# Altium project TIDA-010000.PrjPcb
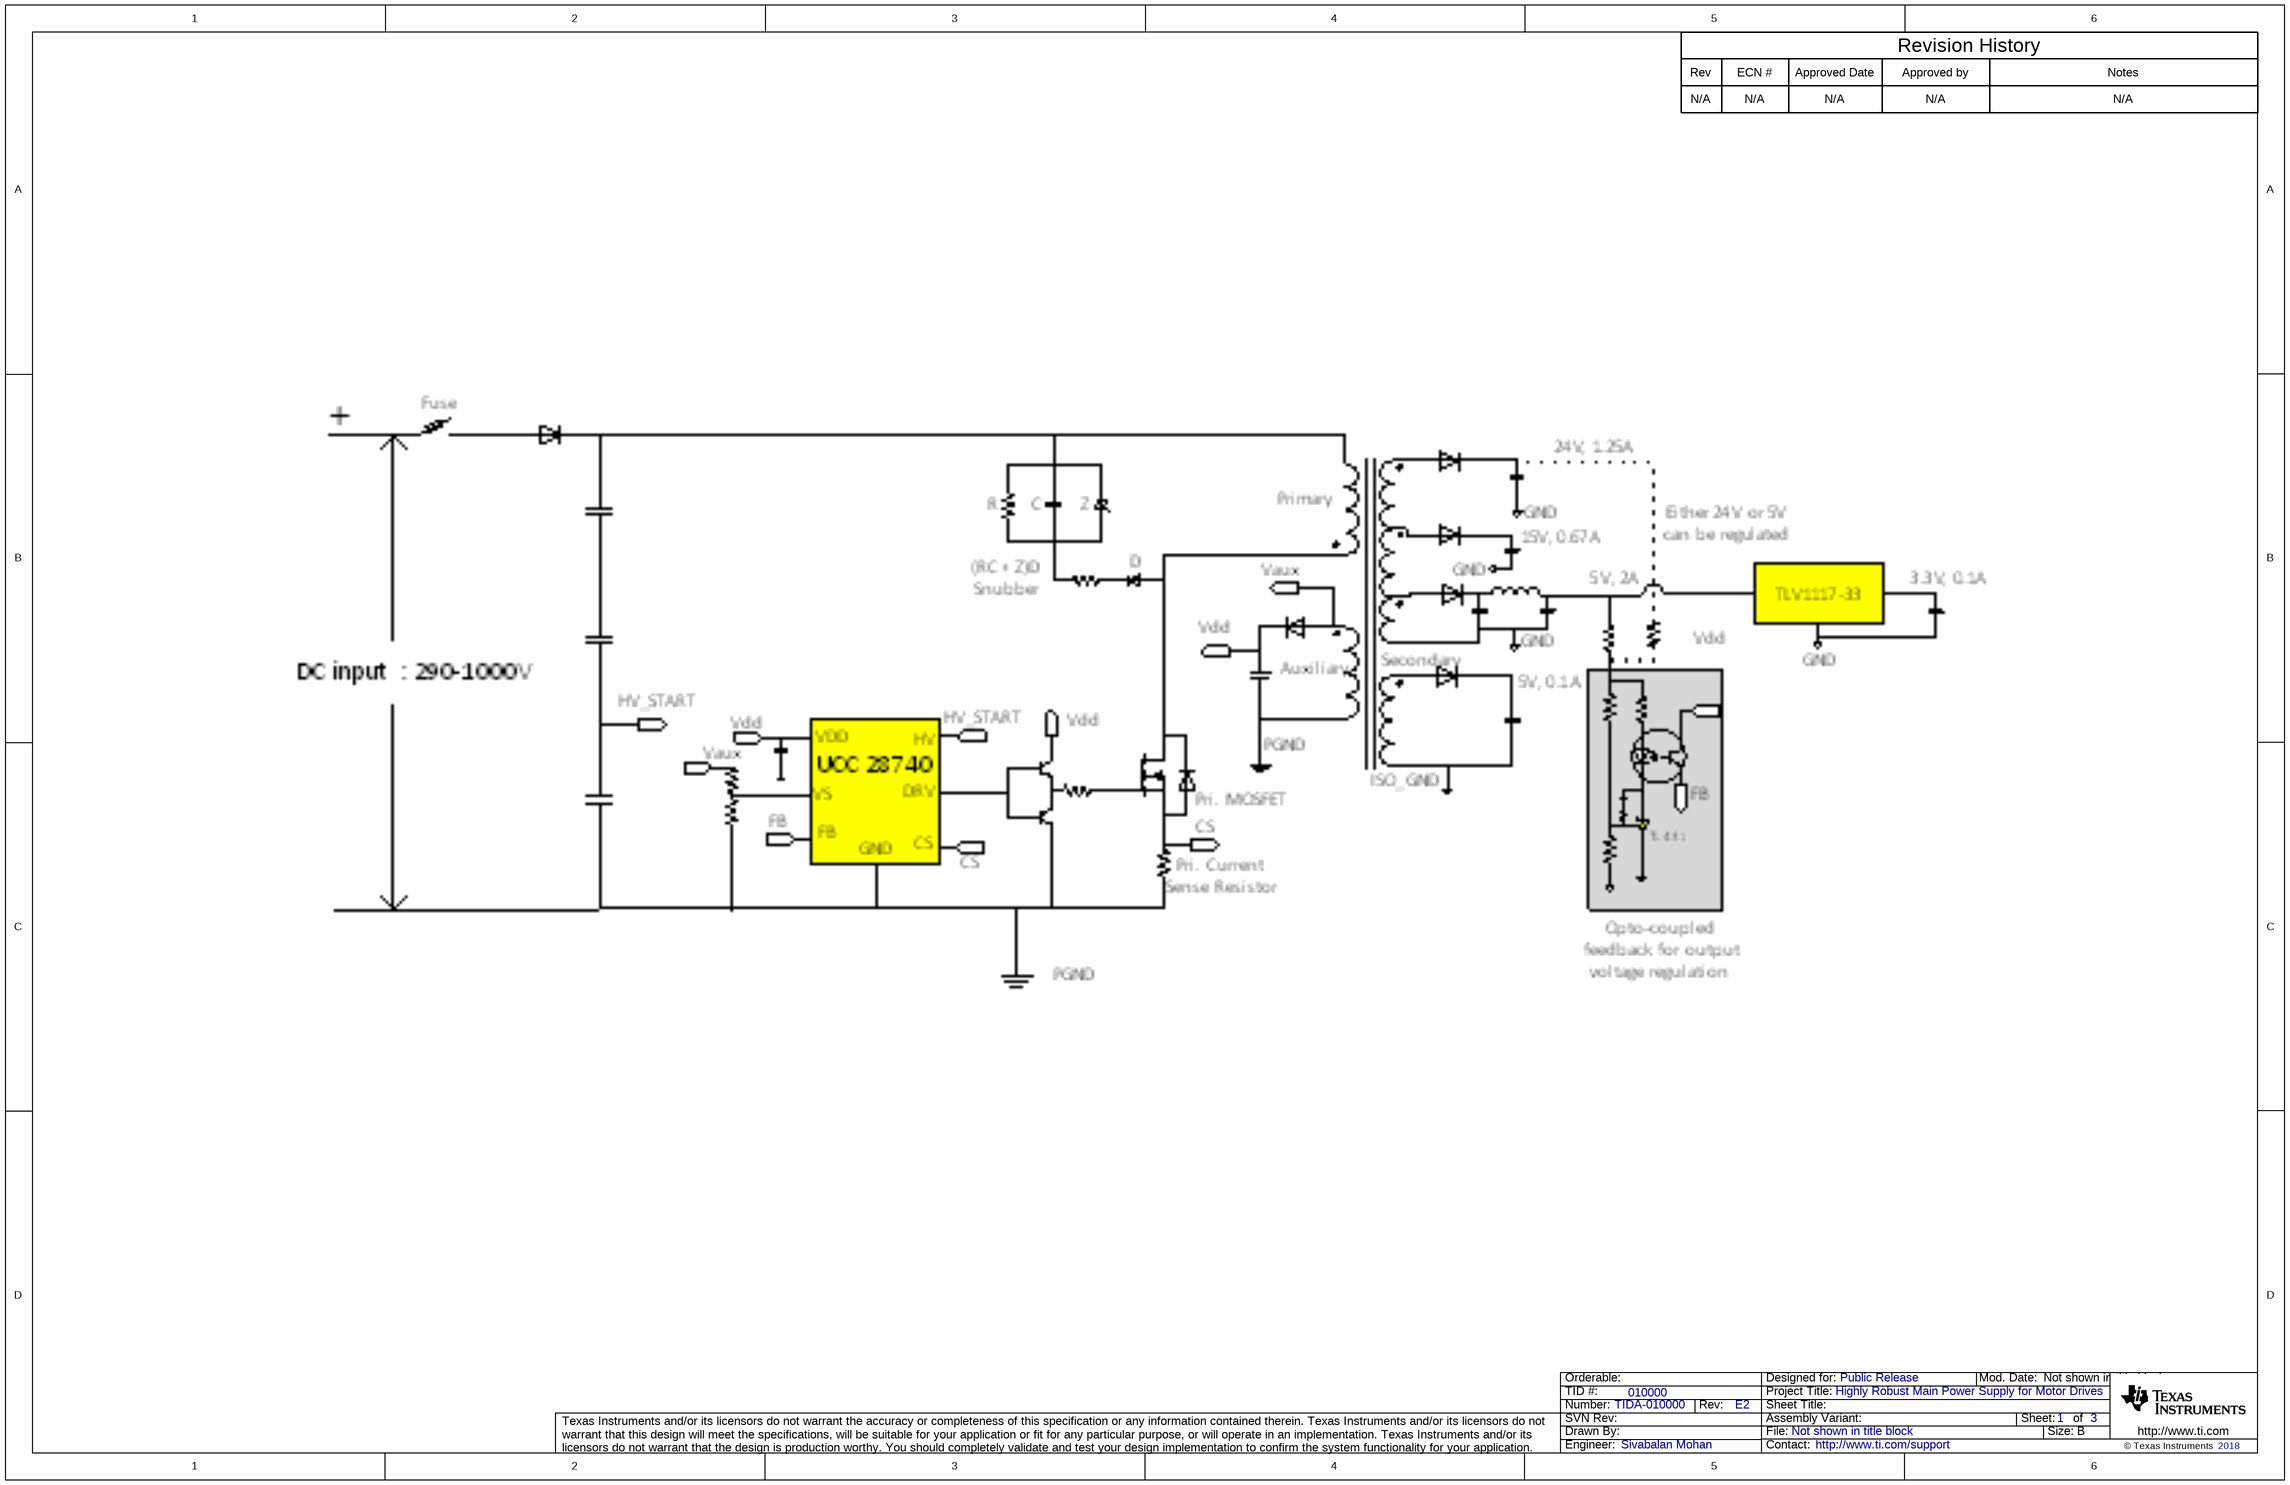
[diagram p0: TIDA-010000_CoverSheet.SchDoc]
CopyrightYear: 2018; PCB_Layout: Shashaank; PCB_Rev: E2; PRJ_Customer: Public Release; PRJ_Engineer: Sivabalan Mohan; PRJ_Number: TIDA-010000; PRJ_Title: Highly Robust Main Power Supply for Motor Drives; SCH_Rev: E2; TechSupport: http://www.ti.com/support; TID: 010000
3 sheets, 147 parts. Net scope: global (net labels, ports and power ports of the same name join across sheets).
Board file: TIDA-010000.PcbDoc
Sheets:
  TIDA-010000_CoverSheet.SchDoc
  TIDA-010000_Flyback Converter.SchDoc
  TIDA-010000_EVM_Hardware.SchDoc

## Sheet TIDA-010000_CoverSheet.SchDoc
size 431 x 279 mm; Date: Not shown in title block; ApprovedBy: Not shown in title block; CheckedBy: Not shown in title block; Author: Not shown in title block; CompanyName: Not shown in title block; Engineer: Not shown in title block; Organization: Not shown in title block; Address1: Not shown in title block; Address2: Not shown in title block; Address3: Not shown in title block; Address4: Not shown in title block; DocumentNumber: 1; Revision: Use project parameter SCH_Rev; SheetNumber: 1; SheetTotal: 3; PageSetup: Record=PageOptions¦CenterHorizontal=True¦CenterVertical=True¦PrintScale=1.00¦XCorrection=1.00¦YCorrection=1.00¦PrintKind=0¦BorderSize=5000000¦LeftOffset=0¦BottomOffset=0¦Orientation=2¦PaperLength=1000¦PaperWidth=1000¦Scale=100¦PaperSource=15¦PrintQuality=600¦MediaType=1¦DitherType=10¦PaperKind=Letter¦PrintScaleMode=1

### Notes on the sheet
- Rev
- N/A
- ECN #
- Approved Date
- Approved by
- Revision History
- Notes

## Sheet TIDA-010000_Flyback Converter.SchDoc
size 431 x 279 mm; Date: Not shown in title block; ApprovedBy: Not shown in title block; CheckedBy: Not shown in title block; Author: Not shown in title block; CompanyName: Not shown in title block; Engineer: Not shown in title block; Organization: Not shown in title block; Address1: Not shown in title block; Address2: Not shown in title block; Address3: Not shown in title block; Address4: Not shown in title block; DocumentNumber: 1; Revision: Use project parameter SCH_Rev; SheetNumber: 2; SheetTotal: 3; PageSetup: Record=PageOptions¦CenterHorizontal=True¦CenterVertical=True¦PrintScale=1.00¦XCorrection=1.00¦YCorrection=1.00¦PrintKind=0¦BorderSize=5000000¦LeftOffset=0¦BottomOffset=0¦Orientation=2¦PaperLength=1000¦PaperWidth=1000¦Scale=100¦PaperSource=15¦PrintQuality=600¦MediaType=1¦DitherType=10¦PaperKind=Letter¦PrintScaleMode=1
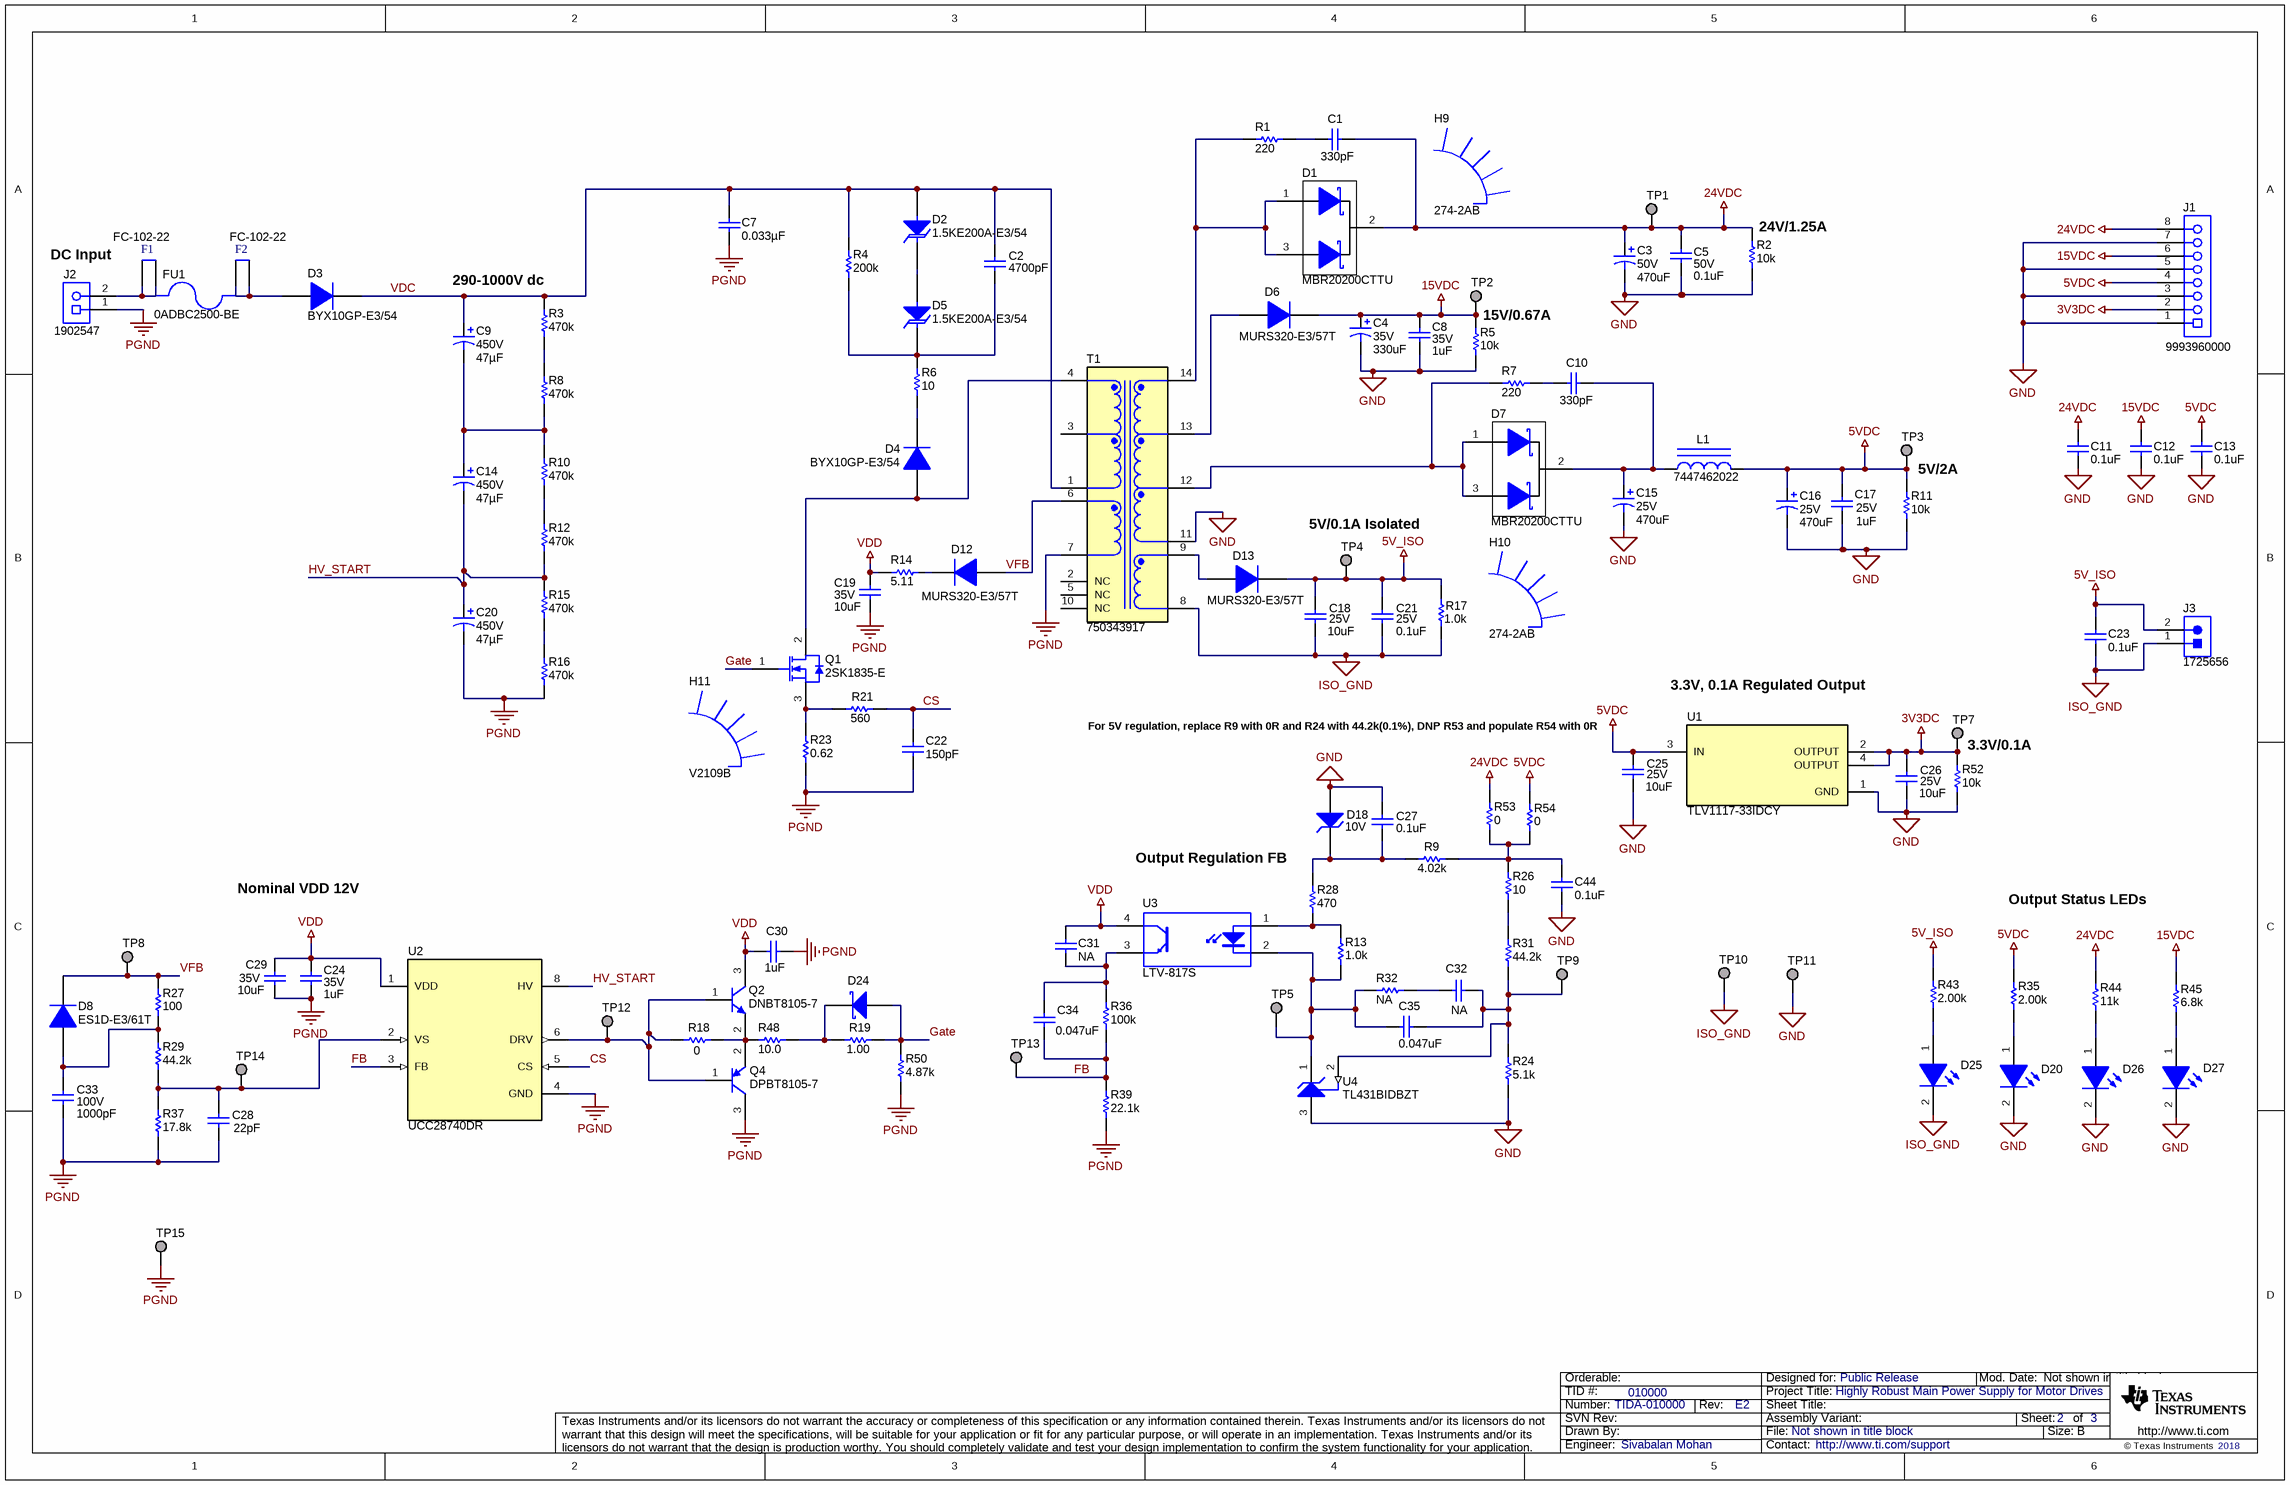
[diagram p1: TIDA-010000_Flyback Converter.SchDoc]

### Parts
C1  ValueDisplayed: 330pF  [1206]  (hidden comment: GRM31A5C2J331JW01D)
C2  ValueDisplayed: 4700pF  [1206]  (hidden comment: GRM31BR73A472KW01L)
C3  VDC_V: 50V  ValueDisplayed: 470uF  [BT_1250x2500]  (hidden comment: UBT1H471MHD1TO)
C4  VDC_V: 35V  ValueDisplayed: 330uF  [BT_1000x2000]  (hidden comment: UBT1V331MPD1TD)
C5  Value2: 50V  ValueDisplayed: 0.1uF  [0805_HV]  (hidden comment: C0805C104K5RACTU)
C7  ValueDisplayed: 0.033µF  [B32672_1800x900x1750]  (hidden comment: B32672L1333J000)
C8  VDC_V: 35V  ValueDisplayed: 1uF  [0603]  (hidden comment: GMK107AB7105KAHT)
C9  VDC_V: 450V  ValueDisplayed: 47µF  [BXW_1250x3500]  (hidden comment: 450BXW47MEFC12.5X35)
C10  ValueDisplayed: 330pF  [1206]  (hidden comment: GRM31A5C2J331JW01D)
C11  ValueDisplayed: 0.1uF  [0805_HV]  (hidden comment: C0805C104K5RACTU)
C12  ValueDisplayed: 0.1uF  [0805_HV]  (hidden comment: C0805C104K5RACTU)
C13  ValueDisplayed: 0.1uF  [0805_HV]  (hidden comment: C0805C104K5RACTU)
C14  VDC_V: 450V  ValueDisplayed: 47µF  [BXW_1250x3500]  (hidden comment: 450BXW47MEFC12.5X35)
C15  VDC_V: 25V  ValueDisplayed: 470uF  [BT_1000x2000]  (hidden comment: UBT1E471MPD1TD)
C16  VDC_V: 25V  ValueDisplayed: 470uF  [BT_1000x2000]  (hidden comment: UBT1E471MPD1TD)
C17  VDC_V: 25V  ValueDisplayed: 1uF  [0805_HV]  (hidden comment: GRM219R71E105KA88D)
C18  VDC_V: 25V  ValueDisplayed: 10uF  [1206_190]  (hidden comment: C3216X7R1E106M160AE)
C19  VDC_V: 35V  ValueDisplayed: 10uF  [1206_180]  (hidden comment: C3216X7R1V106K160AC)
C20  VDC_V: 450V  ValueDisplayed: 47µF  [BXW_1250x3500]  (hidden comment: 450BXW47MEFC12.5X35)
C21  VDC_V: 25V  ValueDisplayed: 0.1uF  [0603]  (hidden comment: C1608X7R1E104K080AA)
C22  ValueDisplayed: 150pF  [0201]  (hidden comment: GRM033R71E151KA01D)
C23  ValueDisplayed: 0.1uF  [0805_HV]  (hidden comment: C0805C104K5RACTU)
C24  VDC_V: 35V  ValueDisplayed: 1uF  [0603]  (hidden comment: GMK107AB7105KAHT)
C25  VDC_V: 25V  ValueDisplayed: 10uF  [1206_190]  (hidden comment: C3216X7R1E106M160AE)
C26  VDC_V: 25V  ValueDisplayed: 10uF  [1206_190]  (hidden comment: C3216X7R1E106M160AE)
C27  ValueDisplayed: 0.1uF  [0805_HV]  (hidden comment: C0805C104K5RACTU)
C28  ValueDisplayed: 22pF  [0201_033]  (hidden comment: GCM0335C1E220JD03D)
C29  VDC_V: 35V  ValueDisplayed: 10uF  [1206_180]  (hidden comment: C3216X7R1V106K160AC)
C30  ValueDisplayed: 1uF  [0603]  (hidden comment: GMK107AB7105KAHT)
C31  ValueDisplayed: NA  [0805_HV]  (hidden comment: C2012X7R1H474K125AB)
C32  ValueDisplayed: NA  [0805_HV]  (hidden comment: C2012X7R1H474K125AB)
C33  Value2: 100V  ValueDisplayed: 1000pF  [0603]  (hidden comment: C1608X7R2A102K080AA)
C34  ValueDisplayed: 0.047uF  [0805_HV]  (hidden comment: 08055C473JAT2A)
C35  ValueDisplayed: 0.047uF  [0805_HV]  (hidden comment: 08055C473JAT2A)
C44  ValueDisplayed: 0.1uF  [0805_HV]  (hidden comment: C0805C104K5RACTU)
D1  MBR20200CTTU  [TO-220AB]
D2  1.5KE200A-E3/54  [DO-201AA_Vertical]
D3  BYX10GP-E3/54  [DO-41]
D4  BYX10GP-E3/54  [DO-41]
D5  1.5KE200A-E3/54  [DO-201AA_Vertical]
D6  MURS320-E3/57T  [SMC]
D7  MBR20200CTTU  [TO-220AB]
D8  ES1D-E3/61T  [SMA]
D12  MURS320-E3/57T  [SMC]
D13  MURS320-E3/57T  [SMC]
D18  value 10V  [SOD-523]  (hidden comment: BZT52C10T-7)
D20  LG L29K-G2J1-24-Z  [LG L29K_GREEN]  (value not drawn)
D24  BAT41ZFILM  [SOD-123]  (value not drawn)
D25  LG L29K-G2J1-24-Z  [LG L29K_GREEN]  (value not drawn)
D26  LG L29K-G2J1-24-Z  [LG L29K_GREEN]  (value not drawn)
D27  LG L29K-G2J1-24-Z  [LG L29K_GREEN]  (value not drawn)
F1  FC-102-22  [BelFuse_FC-102-22]
F2  FC-102-22  [BelFuse_FC-102-22]
FU1  0ADBC2500-BE  (mechanical)
H9  274-2AB  [HSINK_274-2AB]
H10  274-2AB  [HSINK_274-2AB]
H11  V2109B  [Assman_V2109B]
J1  9993960000  [Weidmuller_9993960000]
J2  1902547  [Phoenix_1902547]
J3  1725656  [CONN_1725656]
L1  7447462022  [WE-TI_5075]
Q1  2SK1835-E  [TO-3P]
Q2  DNBT8105-7  [SOT-23]
Q4  DPBT8105-7  [SOT-23]
R1  ValueDisplayed: 220  [2010]  (hidden comment: CRCW2010220RJNEF)
R2  ValueDisplayed: 10k  [1206]  (hidden comment: CRCW120610K0JNEA)
R3  ValueDisplayed: 470k  [1206]  (hidden comment: CRCW1206470KJNEA)
R4  ValueDisplayed: 200k  [PR03]  (hidden comment: PR03000202003JAC00)
R5  ValueDisplayed: 10k  [1206]  (hidden comment: CRCW120610K0JNEA)
R6  ValueDisplayed: 10  [2512]  (hidden comment: ERJ-1TYJ100U)
R7  ValueDisplayed: 220  [2010]  (hidden comment: CRCW2010220RJNEF)
R8  ValueDisplayed: 470k  [1206]  (hidden comment: CRCW1206470KJNEA)
R9  ValueDisplayed: 4.02k  [0805_HV]  (hidden comment: CRCW08054K02FKEA)
R10  ValueDisplayed: 470k  [1206]  (hidden comment: CRCW1206470KJNEA)
R11  ValueDisplayed: 10k  [1206]  (hidden comment: CRCW120610K0JNEA)
R12  ValueDisplayed: 470k  [1206]  (hidden comment: CRCW1206470KJNEA)
R13  ValueDisplayed: 1.0k  [0805_HV]  (hidden comment: CRCW08051K00JNEA)
R14  ValueDisplayed: 5.11  [2512]  (hidden comment: CRCW25125R11FKEG)
R15  ValueDisplayed: 470k  [1206]  (hidden comment: CRCW1206470KJNEA)
R16  ValueDisplayed: 470k  [1206]  (hidden comment: CRCW1206470KJNEA)
R17  ValueDisplayed: 1.0k  [1206]  (hidden comment: CRCW12061K00JNEA)
R18  ValueDisplayed: 0  [1206]  (hidden comment: CRCW12060000Z0EA)
R19  ValueDisplayed: 1.00  [1210]  (hidden comment: CRCW12101R00FKEAHP)
R21  ValueDisplayed: 560  [0805_HV]  (hidden comment: CRCW0805560RJNEA)
R23  ValueDisplayed: 0.62  [2512]  (hidden comment: ERJ-1TRQFR62U)
R24  ValueDisplayed: 5.1k  [0805_HV]  (hidden comment: RT0805BRD075K1L)
R26  ValueDisplayed: 10  [0805_HV]  (hidden comment: CRCW080510R0JNEA)
R27  ValueDisplayed: 100  [0805_HV]  (hidden comment: CRCW0805100RFKEA)
R28  ValueDisplayed: 470  [1206]  (hidden comment: CRCW1206470RJNEA)
R29  ValueDisplayed: 44.2k  [0805_HV]  (hidden comment: CRCW080544K2FKEA)
R31  ValueDisplayed: 44.2k  [0805_HV]  (hidden comment: RT0805BRD0744K2L)
R32  ValueDisplayed: NA  [1206]  (hidden comment: CRCW120610K0JNEA)
R35  ValueDisplayed: 2.00k  [0805_HV]  (hidden comment: CRCW08052K00FKEA)
R36  ValueDisplayed: 100k  [0805_HV]  (hidden comment: CRCW0805100KFKEA)
R37  ValueDisplayed: 17.8k  [0805_HV]  (hidden comment: CRCW080517K8FKEA)
R39  ValueDisplayed: 22.1k  [0805_HV]  (hidden comment: CRCW080522K1FKEA)
R43  ValueDisplayed: 2.00k  [0805_HV]  (hidden comment: CRCW08052K00FKEA)
R44  ValueDisplayed: 11k  [0805_HV]  (hidden comment: CRCW080511K0JNEA)
R45  ValueDisplayed: 6.8k  [0805_HV]  (hidden comment: CRCW08056K80JNEA)
R48  ValueDisplayed: 10.0  [1210]  (hidden comment: CRCW121010R0FKEA)
R50  ValueDisplayed: 4.87k  [1206]  (hidden comment: CRCW12064K87FKEA)
R52  ValueDisplayed: 10k  [1206]  (hidden comment: CRCW120610K0JNEA)
R53  ValueDisplayed: 0  [1206]  (hidden comment: CRCW12060000Z0EA)
R54  ValueDisplayed: 0  [1206]  (hidden comment: CRCW12060000Z0EA)
T1  750343917  [Wurth_ETD34_5455]
TP1  5019  [Keystone_5019]  (value not drawn)
TP2  5019  [Keystone_5019]  (value not drawn)
TP3  5019  [Keystone_5019]  (value not drawn)
TP4  5019  [Keystone_5019]  (value not drawn)
TP5  5019  [Keystone_5019]  (value not drawn)
TP7  5019  [Keystone_5019]  (value not drawn)
TP8  5019  [Keystone_5019]  (value not drawn)
TP9  5019  [Keystone_5019]  (value not drawn)
TP10  5019  [Keystone_5019]  (value not drawn)
TP11  5019  [Keystone_5019]  (value not drawn)
TP12  5019  [Keystone_5019]  (value not drawn)
TP13  5019  [Keystone_5019]  (value not drawn)
TP14  5019  [Keystone_5019]  (value not drawn)
TP15  5019  [Keystone_5019]  (value not drawn)
U1  TLV1117-33IDCY  [DCY0004A_N]
U2  UCC28740DR  [D0007A_N]
U3  LTV-817S  [DIP254P762X350-4]
U4  TL431BIDBZT  [DBZ0003A_N]

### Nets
3V3DC: C26.1 J1.2 R52.2 TP7.1 U1.2(OUTPUT) U1.4(OUTPUT)
5V_ISO: C18.1 C21.1 C23.1 D13.1(K) J3.2 R17.2 R43.2 TP4.1
5VDC: C13.1 C16.1(+) C17.1 C25.1 J1.4 L1.2 R11.2 R35.2 R54.2 TP3.1 U1.3(IN)
15VDC: C4.1(+) C8.1 C12.1 D6.1(K) J1.6 R5.2 R45.2 TP2.1
24VDC: C1.1 C3.1(+) C5.1 C11.1 D1.2(K) J1.8 R2.2 R44.2 R53.2 TP1.1
GND: C3.2(-) C4.2(-) C5.2 C8.2 C11.2 C12.2 C13.2 C15.2(-) C16.2(-) C17.2 C25.2 C26.2 C27.1 C44.2 D18.2(A) D20.2(K) D26.2(K) D27.2(K) J1.1 J1.3 J1.5 J1.7 R2.1 R5.1 R11.1 R24.1 R52.1 T1.11 TP11.1 U1.1(GND) U4.3(ANODE)
ISO_GND: C18.2 C21.2 C23.2 D25.2(K) J3.1 R17.1 T1.8 TP10.1
PGND: C7.2 C19.2 C20.2(-) C22.2 C24.2 C28.2 C29.2 C30.2 C33.2 J2.1 Q4.3(C) R16.1 R23.1 R37.1 R39.1 R50.1 T1.7 TP15.1 U2.4(GND)
VDD: C19.1 C24.1 C29.1 C30.1 C31.1 Q2.3(C) R14.1 U2.1(VDD) U3.4(C)
CS: C22.1 R21.2 U2.5(CS)
FB: C34.2 R36.1 R39.2 TP13.1 U2.3(FB)
Gate: D24.2(A) Q1.1(G) R19.2 R50.2
HV_START: C14.2(-) C20.1(+) R12.1 R15.2 U2.8(HV)
VDC: C2.1 C7.1 C9.1(+) D2.2(A) D3.1(K) R3.2 R4.2 T1.1
VFB: D8.1(K) D12.2(A) R27.2 T1.6 TP8.1
NetC1_2: C1.2 R1.2
NetC2_2: C2.2 D5.1(K) R4.1 R6.2
NetC9_2: C9.2(-) C14.1(+) R8.1 R10.2
NetC10_1: C10.1 C15.1(+) D7.2(K) L1.1
NetC10_2: C10.2 R7.2
NetC27_2: C27.2 D18.1(K) R9.1 R28.2
NetC28_1: C28.1 R29.1 R37.2 TP14.1 U2.2(VS)
NetC31_2: C31.2 C34.1 R36.2 U3.3(E)
NetC32_1: C32.1 C35.2 R24.2 R31.1 TP9.1 U4.2(REF)
NetC32_2: C32.2 R32.1
NetC33_1: C33.1 D8.2(A) R27.1 R29.2
NetC35_1: C35.1 R13.1 R32.2 TP5.1 U3.2(K) U4.1(CATHODE)
NetC44_1: C44.1 R9.2 R26.2 R53.1 R54.1
NetD1_1: D1.1(A) D1.3(A) R1.1 T1.14
NetD2_1: D2.1(K) D5.2(A)
NetD3_2: D3.2(A) F2.1 F2.2
NetD4_1: D4.1(K) R6.1
NetD4_2: D4.2(A) Q1.2(D) T1.4
NetD6_2: D6.2(A) T1.13
NetD7_1: D7.1(A) D7.3(A) R7.1 T1.12
NetD12_1: D12.1(K) R14.2
NetD13_2: D13.2(A) T1.9
NetD20_1: D20.1(A) R35.1
NetD24_1: D24.1(K) R19.1 R48.2
NetD25_1: D25.1(A) R43.1
NetD26_1: D26.1(A) R44.1
NetD27_1: D27.1(A) R45.1
NetF1_1: F1.1 F1.2 J2.2
NetQ1_3: Q1.3(S) R21.1 R23.2
NetQ2_1: Q2.1(B) Q4.1(B) R18.2 TP12.1 U2.6(DRV)
NetQ2_2: Q2.2(E) Q4.2(E) R18.1 R48.1
NetR3_1: R3.1 R8.2
NetR10_1: R10.1 R12.2
NetR13_2: R13.2 R28.1 U3.1(A)
NetR15_1: R15.1 R16.2
NetR26_1: R26.1 R31.2

Not connected (* = marked no-connect by the designer): T1 2(NC) 3 5(NC) 10(NC)

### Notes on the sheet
- (near R2) 24V/1.25A
- DC Input
- (near R3) 290-1000V dc
- 15V/0.67A
- 5V/2A
- (near TP4) 5V/0.1A Isolated
- 3.3V, 0.1A Regulated Output
- (near C25) For 5V regulation, replace R9 with 0R and R24 with 44.2k(0.1%), DNP R53 and populate R54 with 0R
- 3.3V/0.1A
- Nominal VDD 12V
- Output Regulation FB
- Output Status LEDs

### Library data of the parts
C1 C10 = CMP-0008887-2: CAP, CERM, 330 pF, 630 V, +/- 5%, C0G/NP0, 1206; Manufacturer: MuRata; TaMin_C: -55°C; Polarized: N; SizeAreaWB_mm2: 10.92; Value1: Unknown; U/M: EA; Value: 330pF; TaMax_C: 125°C; SizeZ_mm: 1.35; SizeX_mm: 3.2; SizeY_mm: 1.6; Value2: 630V; SizeArea_mm2: 5.12; CompType: Capacitor; AEC Category: Q200
C2 = CMP-0008920-2: CAP, CERM, 4700 pF, 1000 V, +/- 10%, X7R, 1206; Manufacturer: MuRata; TaMin_C: -55°C; Polarized: N; SizeAreaWB_mm2: 10.92; Value1: Unknown; U/M: EA; Value: 4700pF; TaMax_C: 125°C; SizeZ_mm: 1.35; SizeX_mm: 3.2; SizeY_mm: 1.6; Value2: 1000V; SizeArea_mm2: 5.12; CompType: Capacitor; Cap_F: 4.7nF; VDC_V: 1kV; AEC Category: Q200
C3 = CMP-0009919-2: CAP, AL, 470 uF, 50 V, +/- 20%, 0.055 ohm, AEC-Q200 Grade 1, TH; Manufacturer: Nichicon; TaMin_C: -40°C; ESR_ohm: 0.055; Polarized: Y; SizeAreaWB_mm2: 210.25; U/M: EA; Value: 470uF; TaMax_C: 125°C; SizeZ_mm: 27; SizeX_mm: 12.5; Cap_Case: 12.5x25mm; SizeArea_mm2: 156.25; CompType: Capacitor; Cap_F: 470µF; IRMS_A: 1.65A; AEC Grade: 1; AEC Category: Q200
C4 = CMP-0010530-2: CAP, AL, 330 uF, 35 V, +/- 20%, AEC-Q200 Grade 1, TH; Manufacturer: Nichicon; TaMin_C: -40°C; Polarized: Y; SizeAreaWB_mm2: 144; Value1: Unknown; U/M: EA; Value: 330uF; TaMax_C: 125°C; SizeZ_mm: 22; SizeX_mm: 10; Cap_Case: 10x20mm; SizeArea_mm2: 100; CompType: Capacitor; Cap_F: 330µF; AEC Grade: 1; AEC Category: Q200
C5 = CMP-0007726-2: CAP, CERM, 0.1 uF, 50 V, +/- 10%, X7R, 0805; Manufacturer: Kemet; TaMin_C: -55°C; ESR_ohm: 0.064; Polarized: N; SizeAreaWB_mm2: 6.75; Value1: 0.064 ohm; U/M: EA; Value: 0.1uF; TaMax_C: 125°C; SizeZ_mm: 1.45; SizeX_mm: 2; SizeY_mm: 1.25; Cap_Case: 0805; SizeArea_mm2: 2.5; CompType: Capacitor; Cap_F: 100nF; IRMS_A: 1.64A; AEC Category: Q200
C7 = CMP-0080561-1: CAP, Film, 0.033 µF, 1600 V,+/- 5%, TH; Manufacturer: TDK; TaMin_C: -55°C; Polarized: N; SizeAreaWB_mm2: 220; Value: 0.033uF; TaMax_C: 125°C; SizeZ_mm: 17.5; SizeX_mm: 18; SizeY_mm: 9; Cap_Case: 18x9x17.5mm; Value2: 1600V; SizeArea_mm2: 162; CompType: Capacitor; Cap_F: 33nF; VDC_V: 1.6kV; AEC Category: Q200
C8 C24 = CMP-0007149-4: CAP, CERM, 1 uF, 35 V, +/- 10%, X7R, AEC-Q200 Grade 0, 0603; Manufacturer: Taiyo Yuden; TaMin_C: -55°C; Polarized: N; SizeAreaWB_mm2: 4.68; Value1: Unknown; U/M: EA; Value: 1uF; TaMax_C: 125°C; SizeZ_mm: 1; SizeX_mm: 1.6; SizeY_mm: 0.8; SizeArea_mm2: 1.28; CompType: Capacitor; AEC Qualified: Y; Cap_F: 1µF; AEC Grade: 0; AEC Category: Q200
C9 C14 C20 = CMP-0078361-1: CAP, AL, 47 µF, 450 V, +/- 20%, TH; Manufacturer: Rubycon; IRMS_A: 1.2A; SizeAreaWB_mm2: 210.25; SizeArea_mm2: 156.25; AEC Qualified: N; AEC Category: Q200; Value: 47uF; TaMax_C: 105°C; SizeZ_mm: 37; Polarized: Y; TaMin_C: -25°C; SizeY_mm: 12.5; U/M: EA; CompType: Capacitor; Cap_Case: 12.5x35mm
C11-C13 C23 C27 C44 = CMP-0007726-2: CAP, CERM, 0.1 uF, 50 V, +/- 10%, X7R, 0805; Manufacturer: Kemet; TaMin_C: -55°C; ESR_ohm: 0.064; Polarized: N; SizeAreaWB_mm2: 6.75; Value1: 0.064 ohm; U/M: EA; Value: 0.1uF; TaMax_C: 125°C; SizeZ_mm: 1.45; SizeX_mm: 2; SizeY_mm: 1.25; Cap_Case: 0805; Value2: 50V; SizeArea_mm2: 2.5; CompType: Capacitor; Cap_F: 100nF; IRMS_A: 1.64A; AEC Category: Q200
C15 C16 = CMP-0010529-1: CAP, AL, 470 uF, 25 V, +/- 20%, 0.057 ohm, TH; Manufacturer: Nichicon; TaMin_C: -40°C; ESR_ohm: 0.057; Polarized: Y; SizeAreaWB_mm2: 144; U/M: EA; Value: 470uF; TaMax_C: 125°C; SizeZ_mm: 22; SizeX_mm: 10; Cap_Case: 10x20mm; SizeArea_mm2: 100; CompType: Capacitor; Cap_F: 470µF; IRMS_A: 1.1A; AEC Category: Q200
C17 = CMP-0008217-2: CAP, CERM, 1 uF, 25 V, +/- 10%, X7R, 0805; Manufacturer: MuRata; TaMin_C: -55°C; Polarized: N; SizeAreaWB_mm2: 6.75; Value1: Unknown; U/M: EA; Value: 1uF; TaMax_C: 125°C; SizeZ_mm: 1.45; SizeX_mm: 2; SizeY_mm: 1.25; Cap_Case: 0805; SizeArea_mm2: 2.5; CompType: Capacitor; Cap_F: 1µF; AEC Category: Q200
C18 C25 C26 = CMP-0008692-2: CAP, CERM, 10 uF, 25 V, +/- 20%, X7R, 1206_190; Manufacturer: TDK; TaMin_C: -55°C; Polarized: N; SizeAreaWB_mm2: 10.92; Value1: Unknown; U/M: EA; Value: 10uF; TaMax_C: 125°C; SizeZ_mm: 1.9; SizeX_mm: 3.2; SizeY_mm: 1.6; Cap_Case: 1206; SizeArea_mm2: 5.12; Cap_F: 10µF; AEC Category: Q200
C19 C29 = CMP-0008705-2: CAP, CERM, 10 uF, 35 V, +/- 10%, X7R, 1206; Manufacturer: TDK; TaMin_C: -55°C; ESR_ohm: 2.229m; Polarized: N; SizeAreaWB_mm2: 10.92; Value1: 0.002229 ohm; U/M: EA; Value: 10uF; TaMax_C: 125°C; SizeZ_mm: 1.8; SizeX_mm: 3.2; SizeY_mm: 1.6; SizeArea_mm2: 5.12; CompType: Capacitor; Cap_F: 10µF; IRMS_A: 4.85932A; AEC Category: Q200
C21 = CMP-0007039-5: CAP, CERM, 0.1 uF, 25 V, +/- 10%, X7R, 0603; Manufacturer: TDK; TaMin_C: -55°C; Polarized: N; SizeAreaWB_mm2: 4.68; Value1: Unknown; U/M: EA; Value: 0.1uF; TaMax_C: 125°C; SizeZ_mm: 1; SizeX_mm: 1.6; SizeY_mm: 0.8; SizeArea_mm2: 1.28; Cap_F: 100nF; AEC Category: Q200
C22 = CMP-0009767-1: CAP, CERM, 150 pF, 25 V, +/- 10%, X7R, 0201; Manufacturer: MuRata; TaMin_C: -55°C; Polarized: N; SizeAreaWB_mm2: 2.08; Value1: Unknown; U/M: EA; Value: 150pF; TaMax_C: 125°C; SizeZ_mm: 0.26; SizeX_mm: 0.6; SizeY_mm: 0.3; Value2: 25V; SizeArea_mm2: 0.18; CompType: Capacitor; AEC Category: Q200
C28 = CMP-0009659-3: CAP, CERM, 22 pF, 25 V, +/- 5%, C0G/NP0, AEC-Q200 Grade 1, 0201; Manufacturer: MuRata; TaMin_C: -55°C; Polarized: N; SizeAreaWB_mm2: 2.08; Value1: Unknown; U/M: EA; Value: 22pF; TaMax_C: 125°C; SizeZ_mm: 0.33; SizeX_mm: 0.6; SizeY_mm: 0.3; Cap_Case: 0201; Value2: 25V; SizeArea_mm2: 0.18; CompType: Capacitor; AEC Qualified: Y; AEC Grade: 1; AEC Category: Q200
C30 = CMP-0007149-4: CAP, CERM, 1 uF, 35 V, +/- 10%, X7R, AEC-Q200 Grade 0, 0603; Manufacturer: Taiyo Yuden; TaMin_C: -55°C; Polarized: N; SizeAreaWB_mm2: 4.68; Value1: Unknown; U/M: EA; Value: 1uF; TaMax_C: 125°C; SizeZ_mm: 1; SizeX_mm: 1.6; SizeY_mm: 0.8; Value2: 35V; SizeArea_mm2: 1.28; CompType: Capacitor; AEC Qualified: Y; Cap_F: 1µF; AEC Grade: 0; AEC Category: Q200
C31 C32 = CMP-0007880-2: CAP, CERM, 0.47 uF, 50 V, +/- 10%, X7R, 0805; Manufacturer: TDK; TaMin_C: -55°C; ESR_ohm: 0.022012; Polarized: N; SizeAreaWB_mm2: 6.75; Value1: 0.022012 ohm; U/M: EA; Value: 0.47uF; TaMax_C: 125°C; SizeZ_mm: 1.45; SizeX_mm: 2; SizeY_mm: 1.25; Cap_Case: 0805; Value2: 50V; SizeArea_mm2: 2.5; CompType: Capacitor; Cap_F: 470nF; IRMS_A: 1.39566A; AEC Category: Q200
C33 = CMP-0007053-4: CAP, CERM, 1000 pF, 100 V, +/- 10%, X7R, 0603; Manufacturer: TDK; TaMin_C: -55°C; Polarized: N; SizeAreaWB_mm2: 4.68; Value1: Unknown; U/M: EA; Value: 1000pF; TaMax_C: 125°C; SizeZ_mm: 1; SizeX_mm: 1.6; SizeY_mm: 0.8; SizeArea_mm2: 1.28; CompType: Capacitor; Cap_F: 1nF; AEC Category: Q200
C34 C35 = CMP-0007658-2: CAP, CERM, 0.047 uF, 50 V, +/- 5%, X7R, 0805; Manufacturer: AVX; TaMin_C: -55°C; ESR_ohm: 0.035; Polarized: N; SizeAreaWB_mm2: 6.75; Value1: 0.035 ohm; U/M: EA; TaMax_C: 125°C; SizeZ_mm: 1.45; SizeX_mm: 2; SizeY_mm: 1.25; Cap_Case: 0805; Value2: 50V; SizeArea_mm2: 2.5; CompType: Capacitor; Cap_F: 47nF; AEC Category: Q200
D1 D7 = CMP-0077060-2: Diode, Schottky, 200 V, 10 A, TH; Manufacturer: Fairchild Semiconductor; SizeAreaWB_mm2: 79.3; Vr_V: 200V; SizeArea_mm2: 45.9; AEC Qualified: N; TJmax_C: 150°C; AEC Category: Q101; Value: 200V; SizeZ_mm: 19.4; Green_REACh: Incomplete; Io_A: 10A; Vf_V: 9dV; SizeY_mm: 4.5; Value2: 0.9V; Green_Lifecycle: Not Set; U/M: EA; SizeX_mm: 10.2; RJC_CperW: 1.5
D2 D5 = CMP-0082199-2: Diode, TVS, Uni, 200 V, 274 Vc, AEC-Q101, DO-201AA; Manufacturer: Vishay-Semiconductor; Value: 200V; AEC Qualified: Y; SizeZ_mm: 5.3; SizeX_mm: 15.59; SizeAreaWB_mm2: 88.87; SizeArea_mm2: 78.73; AEC Category: Q101; RJA_CperW: 75; SizeY_mm: 5.05
D3 D4 = CMP-0082148-1: Diode, Standard Recovery Rectifier, 1600 V, 0.36 A, TH; Manufacturer: Vishay-Semiconductor; SizeAreaWB_mm2: 43.424; Vr_V: 1.6kV; SizeArea_mm2: 19.584; AEC Qualified: N; TJmax_C: 175°C; AEC Category: Q101; Value: 1600V; SizeZ_mm: 23.4; Io_A: 3.6dA; Vf_V: 1.6V; SizeY_mm: 2.72; Value1: 0.36A; SizeX_mm: 7.2
D6 D13 = CMP-0082145-1: Diode, Ultrafast, 200 V, 3 A, AEC-Q101, SMC; Manufacturer: Vishay-Semiconductor; SizeAreaWB_mm2: 83.2686; Vr_V: 200V; SizeArea_mm2: 50.5686; AEC Qualified: Y; TJmax_C: 175°C; AEC Category: Q101; Value: 200V; SizeZ_mm: 2.62; Io_A: 3A; Vf_V: 8.75dV; SizeY_mm: 6.22; Value2: 0.875V; SizeX_mm: 8.13
D8 = CMP-0082147-1: Diode, Ultrafast, 200 V, 1 A, AEC-Q101, SMA; Manufacturer: Vishay-Semiconductor; SizeAreaWB_mm2: 37.3428; Vr_V: 200V; SizeArea_mm2: 16.3228; AEC Qualified: Y; TJmax_C: 150°C; AEC Category: Q101; Value: 200V; SizeZ_mm: 2.87; Io_A: 1A; Vf_V: 9.2dV; SizeY_mm: 2.92; Value2: 0.92V; SizeX_mm: 5.59
D12 = CMP-0082145-1: Diode, Ultrafast, 200 V, 3 A, AEC-Q101, SMC; Manufacturer: Vishay-Semiconductor; Value: 200V; SizeAreaWB_mm2: 83.2686; SizeArea_mm2: 50.5686; AEC Qualified: Y; TJmax_C: 175°C; AEC Category: Q101; SizeZ_mm: 2.62; Io_A: 3A; Vf_V: 8.75dV; SizeY_mm: 6.22; Value2: 0.875V; SizeX_mm: 8.13
D18 = CMP-0005875-3: Diode, Zener, 10 V, 300 mW, SOD-523; Manufacturer: Diodes Inc.; Power_W: 300mW; SizeAreaWB_mm2: 5.13; Value1: 0.3W; RJA_CperW: 417; U/M: EA; SizeZ_mm: 0.65; SizeX_mm: 1.7; SizeY_mm: 0.9; SizeArea_mm2: 1.53; AEC Category: Q101
D20 D25-D27 = CMP-0002874-1: LED, Green, SMD; Manufacturer: OSRAM; Io_A: 2mA; Tjmax_C: 110°C; Value1: W; U/M: EA; Vf_V: 1.7V
D24 = CMP-0028445-1: Diode, Schottky, 100 V, 0.2 A, SOD-123; Manufacturer: STMicroelectronics; Io_A: 2dA; Green_Lifecycle: Active; SizeAreaWB_mm2: 13.095; Vr_V: 100V; Green_REACh: Passed; Value1: 0.2A; TJmax_C: 150°C; U/M: EA; Value: 100V; SizeZ_mm: 1.35; SizeX_mm: 3.85; SizeY_mm: 1.7; Vf_V: 1V; SizeArea_mm2: 6.545; AEC Category: Q101
F1 F2 = CMP-0082195-1: FUSE CLIP CARTRIDGE 15A PCB; Manufacturer: Bel Fuse; CompType: Fuse Holder
FU1 = CMP-0082235-1: Fuse, 2.5 A, 1000VAC/VDC, Cartridge; Manufacturer: Bel Fuse; TaMin_C: -50°C; Irating_A: 2.5A; Interrupt_AC: 10kA; VAC_V: 1kV; TaMax_C: 105°C; Fuse Speed: Fast; Rtyp_Ohm: 0.089; MeltingTyp: 3.91
H9 H10 = CMP-0084022-1: HEATSINK LOW HEIGHT BLK TO-220; Manufacturer: Wakefield-Vette
H11 = CMP-0082194-1: Heat Sink TO-220 Aluminum Board Level; Manufacturer: Assman WSW
J1 = CMP-0075186-1: Terminal Block, 5.08mm, 8x1, Black, TH; Manufacturer: Weidmuller; CNHeader: False; Current_A: 18A; Gender: Female; Cert_CSA: Y; Voltage_V: 300V; Row_Count: 1; Pitch_mm: 5.08; CT: True
J2 = CMP-0055527-1: Terminal Block, 9.52mm, 2x1, R/A, TH; Manufacturer: Phoenix Contact; Cert_VDE: Y; CNHeader: FALSE; Current_A: 32A; Gender: Female; Voltage_V: 1kV; Row_Count: 1; Pitch_mm: 9.52; CT: TRUE
J3 = CMP-0055479-1: Terminal Block, 100mil, 2x1, 6A, 63V, TH; Manufacturer: Phoenix Contact; CNHeader: FALSE; Green_Lifecycle: Not Set; Green_REACh: Incomplete; CT: TRUE
L1 = CMP-0064180-1: Inductor, Unshielded Drum Core, Ferrite, 2.2 uH, 4.3 A, 0.01 ohm, TH; Manufacturer: Wurth Elektronik; Isat: 4.3A @ 10% inductance drop; Irms: 6.3A @ 40C rise; Green_Lifecycle: Active; SizeAreaWB_mm2: 64; DCR_ohm: 0.01; Green_REACh: Passed; Value: 2.2uH; Imax_A: 4.3A; SizeZ_mm: 8.5; SizeX_mm: 6; SizeArea_mm2: 36; Ind_H: 2.2µH; AEC Category: Q200
Q1 = CMP-0082176-1: MOSFET, N-CH, 1500 V, 4 A, TO-3P; Manufacturer: Renesas; Alternate Manufacturer: None; ChType: N; SizeAreaWB_mm2: 120.02; SizeArea_mm2: 75.12; IdsMax_A: 4A; VdsMax_V: 1.5kV; Vgs_V: 20V; AEC Category: Q101; Value: 1500V; SizeZ_mm: 23.9; ChMode: Enhancement; SizeY_mm: 4.8; Value2: ? nC; Value1: ? ohm; SizeX_mm: 15.65
Q2 = CMP-0064871-1: Transistor, NPN, 60 V, 1 A, AEC-Q101, SOT-23; Manufacturer: Diodes Inc.; TaMin_C: -55°C; HfeMax: 300; Green_Lifecycle: Not Set; SizeAreaWB_mm2: 14; Green_REACh: Incomplete; Value1: 1 A; Vceo_V: 60V; U/M: EA; Value: 60 V; TaMax_C: 150°C; IcRated_A: 1A; SizeZ_mm: 1.1; SizeX_mm: 2.5; SizeY_mm: 3; SizeArea_mm2: 7.5; CompType: BJT; PNP: 0; AEC Qualified: Y; NPN: 1; Vcesat1_V: 2.5dV; AEC Category: Q101
Q4 = CMP-0064870-1: Transistor, PNP, 60 V, 1 A, AEC-Q101, SOT-23; Manufacturer: Diodes Inc.; TaMin_C: -55°C; HfeMax: 300; SizeAreaWB_mm2: 14; Value1: 1 A; Vceo_V: 60V; U/M: EA; Value: 60 V; TaMax_C: 150°C; IcRated_A: 1A; SizeZ_mm: 1.1; SizeX_mm: 2.5; SizeY_mm: 3; SizeArea_mm2: 7.5; CompType: BJT; PNP: 1; AEC Qualified: Y; NPN: 0; Vcesat1_V: 3dV; AEC Category: Q101
R1 R7 = CMP-0016095-3: RES, 220, 5%, 0.75 W, AEC-Q200 Grade 0, 2010; Manufacturer: Vishay-Dale; Power_W: 750mW; TempCo: 200 ppm/C; Value_Code: 220R; Value: 220; EIA_Code: E24; SizeX_mm: 5; SizeY_mm: 2.5; SizeZ_mm: 1.66; Value2: 0.75W; SizeArea_mm2: 12.5; AEC Qualified: Y; VDC_V: 400V; AEC Grade: 0; AEC Category: Q200
R2 R5 R11 = CMP-0018576-3: RES, 10 k, 5%, 0.25 W, AEC-Q200 Grade 0, 1206; Manufacturer: Vishay-Dale; Power_W: 250mW; TempCo: 200 ppm/C; Value_Code: 10k0; Value: 10k; EIA_Code: E24; SizeX_mm: 3.2; SizeY_mm: 1.6; SizeZ_mm: 1.35; Value2: 0.25W; SizeArea_mm2: 5.12; AEC Qualified: Y; VDC_V: 200V; AEC Category: Q200; AEC Grade: 0
R3 R8 R10 R12 R15 R16 = CMP-0018684-3: RES, 470 k, 5%, 0.25 W, AEC-Q200 Grade 0, 1206; Manufacturer: Vishay-Dale; Power_W: 250mW; TempCo: 200 ppm/C; Value: 470k; EIA_Code: E24; SizeX_mm: 3.2; SizeY_mm: 1.6; SizeZ_mm: 1.35; Value2: 0.25W; SizeArea_mm2: 5.12; AEC Qualified: Y; VDC_V: 200V; AEC Category: Q200; AEC Grade: 0
R4 = CMP-0014434-2: RES, 200 k, 5%, 3 W, D5.20xL16.70mm; Manufacturer: Vishay-Bccomponents; Power_W: 3W; TempCo: 250 ppm/C; U/M: EA; Value: 200k; EIA_Code: E24; CompType: Resistor; AEC Qualified: N; VDC_V: 750V; AEC Category: Q200
R6 = CMP-0016023-2: RES, 10, 5%, 1 W, 2512; Manufacturer: Panasonic; Power_W: 1W; TempCo: 200 ppm/C; Value_Code: 10R0; U/M: EA; Value: 10; EIA_Code: E24; SizeX_mm: 6.3; SizeY_mm: 3.2; SizeZ_mm: 0.71; SizeArea_mm2: 20.16; CompType: Resistor; VDC_V: 200V; AEC Category: Q200
R9 = CMP-0021285-3: RES, 4.02 k, 1%, 0.125 W, AEC-Q200 Grade 0, 0805; Manufacturer: Vishay-Dale; Power_W: 125mW; TempCo: 100 ppm/C; Value_Code: 4k02; Value: 4.02k; EIA_Code: E96; SizeX_mm: 2; SizeY_mm: 1.25; SizeZ_mm: 1.45; Value2: 0.125W; SizeArea_mm2: 2.5; CompType: Resistor; AEC Qualified: Y; VDC_V: 150V; AEC Category: Q200; AEC Grade: 0
R13 = CMP-0020473-3: RES, 1.0 k, 5%, 0.125 W, AEC-Q200 Grade 0, 0805; Manufacturer: Vishay-Dale; Power_W: 125mW; TempCo: 200 ppm/C; Value_Code: 1k00; Value: 1.0k; EIA_Code: E24; Res_ohm: 1k; SizeX_mm: 2; SizeY_mm: 1.25; SizeZ_mm: 1.45; Value2: 0.125W; SizeArea_mm2: 2.5; AEC Qualified: Y; VDC_V: 150V; AEC Category: Q200; AEC Grade: 0
R14 = CMP-0015688-3: RES, 5.11, 1%, 1 W, AEC-Q200 Grade 0, 2512; Manufacturer: Vishay-Dale; Power_W: 1W; TempCo: 100 ppm/C; Value_Code: 5R11; Value: 5.11; EIA_Code: E96; SizeX_mm: 6.3; SizeY_mm: 3.2; SizeZ_mm: 0.71; SizeArea_mm2: 20.16; AEC Qualified: Y; VDC_V: 500V; AEC Grade: 0; AEC Category: Q200
R17 = CMP-0018603-3: RES, 1.0 k, 5%, 0.25 W, AEC-Q200 Grade 0, 1206; Manufacturer: Vishay-Dale; Power_W: 250mW; TempCo: 200 ppm/C; Value_Code: 1k00; Value: 1.0k; EIA_Code: E24; Res_ohm: 1k; SizeX_mm: 3.2; SizeY_mm: 1.6; SizeZ_mm: 1.35; Value2: 0.25W; SizeArea_mm2: 5.12; CompType: Resistor; AEC Qualified: Y; VDC_V: 200V; AEC Category: Q200; AEC Grade: 0
R18 R53 R54 = CMP-0018573-3: RES, 0, 5%, 0.25 W, AEC-Q200 Grade 0, 1206; Manufacturer: Vishay-Dale; Power_W: 250mW; TempCo: 200 ppm/C; Value_Code: 0000; Value: 0; EIA_Code: E24; SizeX_mm: 3.2; SizeY_mm: 1.6; SizeZ_mm: 1.35; Value2: 0.25W; SizeArea_mm2: 5.12; CompType: Resistor; AEC Qualified: Y; VDC_V: 200V; AEC Category: Q200
R19 = CMP-0015021-3: RES, 1.00, 1%, 0.75 W, AEC-Q200 Grade 0, 1210; Manufacturer: Vishay-Dale; Power_W: 750mW; TempCo: 100 ppm/C; SizeAreaWB_mm2: 14.7; Value_Code: 1R00; Value: 1.00; EIA_Code: E96; Res_ohm: 1; SizeX_mm: 3.2; SizeY_mm: 2.5; SizeZ_mm: 1.35; Value2: 0.75W; SizeArea_mm2: 8; AEC Qualified: Y; AEC Grade: 0; AEC Category: Q200
R21 = CMP-0020569-3: RES, 560, 5%, 0.125 W, AEC-Q200 Grade 0, 0805; Manufacturer: Vishay-Dale; Power_W: 125mW; TempCo: 200 ppm/C; Value_Code: 560R; Value: 560; EIA_Code: E24; SizeX_mm: 2; SizeY_mm: 1.25; SizeZ_mm: 1.45; Value2: 0.125W; SizeArea_mm2: 2.5; AEC Qualified: Y; VDC_V: 150V; AEC Category: Q200; AEC Grade: 0
R23 = CMP-0015803-2: RES, 0.62, 1%, 1 W, 2512; Manufacturer: Panasonic; Power_W: 1W; TempCo: 200 ppm/C; Value_Code: R620; U/M: EA; Value: 0.62; EIA_Code: E96; Res_ohm: 6.2d; SizeX_mm: 6.3; SizeY_mm: 3.2; SizeZ_mm: 0.71; SizeArea_mm2: 20.16; AEC Category: Q200
R24 = CMP-0082196-1: RES, 5.10 k, 0.1%, 0.125 W, 0805; Manufacturer: Yageo; Value_Code: 5k10; SizeAreaWB_mm2: 6.75; SizeArea_mm2: 2.5; AEC Qualified: N; AEC Category: Q200; Value: 5.10k; SizeZ_mm: 1.45; TempCo: 25 ppm/C; Power_W: 125mW; VDC_V: 150V; SizeY_mm: 1.25; Value2: 0.125W; CompType: Resistor; SizeX_mm: 2
R26 = CMP-0020448-3: RES, 10, 5%, 0.125 W, AEC-Q200 Grade 0, 0805; Manufacturer: Vishay-Dale; Power_W: 125mW; TempCo: 200 ppm/C; Value_Code: 10R0; Value: 10; EIA_Code: E24; SizeX_mm: 2; SizeY_mm: 1.25; SizeZ_mm: 1.45; Value2: 0.125W; SizeArea_mm2: 2.5; AEC Qualified: Y; VDC_V: 150V; AEC Category: Q200; AEC Grade: 0
R27 = CMP-0020835-3: RES, 100, 1%, 0.125 W, AEC-Q200 Grade 0, 0805; Manufacturer: Vishay-Dale; Power_W: 125mW; TempCo: 100 ppm/C; Value_Code: 100R; Value: 100; EIA_Code: E96; SizeX_mm: 2; SizeY_mm: 1.25; SizeZ_mm: 1.45; Value2: 0.125W; SizeArea_mm2: 2.5; CompType: Resistor; AEC Qualified: Y; VDC_V: 150V; AEC Category: Q200; AEC Grade: 0
R28 = CMP-0018685-3: RES, 470, 5%, 0.25 W, AEC-Q200 Grade 0, 1206; Manufacturer: Vishay-Dale; Power_W: 250mW; TempCo: 200 ppm/C; Value_Code: 470R; Value: 470; EIA_Code: E24; SizeX_mm: 3.2; SizeY_mm: 1.6; SizeZ_mm: 1.35; Value2: 0.25W; SizeArea_mm2: 5.12; CompType: Resistor; AEC Qualified: Y; VDC_V: 200V; AEC Category: Q200; AEC Grade: 0
R29 = CMP-0021262-3: RES, 44.2 k, 1%, 0.125 W, AEC-Q200 Grade 0, 0805; Manufacturer: Vishay-Dale; Power_W: 125mW; TempCo: 100 ppm/C; Value_Code: 44k2; Value: 44.2k; EIA_Code: E96; SizeX_mm: 2; SizeY_mm: 1.25; SizeZ_mm: 1.45; Value2: 0.125W; SizeArea_mm2: 2.5; CompType: Resistor; AEC Qualified: Y; VDC_V: 150V; AEC Category: Q200; AEC Grade: 0
R31 = CMP-0020087-2: RES, 44.2 k, 0.1%, 0.125 W, 0805; Manufacturer: Yageo America; Power_W: 125mW; TempCo: 25 ppm/C; Value_Code: 44k2; U/M: EA; Value: 44.2k; EIA_Code: E192; SizeX_mm: 2; SizeY_mm: 1.25; SizeZ_mm: 1.45; Value2: 0.125W; SizeArea_mm2: 2.5; VDC_V: 150V; AEC Category: Q200
R32 R52 = CMP-0018576-3: RES, 10 k, 5%, 0.25 W, AEC-Q200 Grade 0, 1206; Manufacturer: Vishay-Dale; Power_W: 250mW; TempCo: 200 ppm/C; Value_Code: 10k0; Value: 10k; EIA_Code: E24; SizeX_mm: 3.2; SizeY_mm: 1.6; SizeZ_mm: 1.35; Value2: 0.25W; SizeArea_mm2: 5.12; CompType: Resistor; AEC Qualified: Y; VDC_V: 200V; AEC Category: Q200; AEC Grade: 0
R35 R43 = CMP-0021106-3: RES, 2.00 k, 1%, 0.125 W, AEC-Q200 Grade 0, 0805; Manufacturer: Vishay-Dale; Power_W: 125mW; TempCo: 100 ppm/C; Value_Code: 2k00; Value: 2.00k; EIA_Code: E96; Res_ohm: 2k; SizeX_mm: 2; SizeY_mm: 1.25; SizeZ_mm: 1.45; Value2: 0.125W; SizeArea_mm2: 2.5; CompType: Resistor; AEC Qualified: Y; VDC_V: 150V; AEC Category: Q200; AEC Grade: 0
R36 = CMP-0020834-3: RES, 100 k, 1%, 0.125 W, AEC-Q200 Grade 0, 0805; Manufacturer: Vishay-Dale; Power_W: 125mW; TempCo: 100 ppm/C; Value: 100k; EIA_Code: E96; SizeX_mm: 2; SizeY_mm: 1.25; SizeZ_mm: 1.45; Value2: 0.125W; SizeArea_mm2: 2.5; AEC Qualified: Y; VDC_V: 150V; AEC Category: Q200; AEC Grade: 0
R37 = CMP-0020932-3: RES, 17.8 k, 1%, 0.125 W, AEC-Q200 Grade 0, 0805; Manufacturer: Vishay-Dale; Power_W: 125mW; TempCo: 100 ppm/C; Value_Code: 17k8; Value: 17.8k; EIA_Code: E96; SizeX_mm: 2; SizeY_mm: 1.25; SizeZ_mm: 1.45; Value2: 0.125W; SizeArea_mm2: 2.5; CompType: Resistor; AEC Qualified: Y; VDC_V: 150V; AEC Category: Q200; AEC Grade: 0
R39 = CMP-0021058-3: RES, 22.1 k, 1%, 0.125 W, AEC-Q200 Grade 0, 0805; Manufacturer: Vishay-Dale; Power_W: 125mW; TempCo: 100 ppm/C; Value_Code: 22k1; Value: 22.1k; EIA_Code: E96; SizeX_mm: 2; SizeY_mm: 1.25; SizeZ_mm: 1.45; Value2: 0.125W; SizeArea_mm2: 2.5; AEC Qualified: Y; VDC_V: 150V; AEC Category: Q200; AEC Grade: 0
R44 = CMP-0020451-3: RES, 11 k, 5%, 0.125 W, AEC-Q200 Grade 0, 0805; Manufacturer: Vishay-Dale; Power_W: 125mW; TempCo: 200 ppm/C; Value_Code: 11k0; Value: 11k; EIA_Code: E24; SizeX_mm: 2; SizeY_mm: 1.25; SizeZ_mm: 1.45; Value2: 0.125W; SizeArea_mm2: 2.5; AEC Qualified: Y; VDC_V: 150V; AEC Category: Q200; AEC Grade: 0
R45 = CMP-0020587-3: RES, 6.8 k, 5%, 0.125 W, AEC-Q200 Grade 0, 0805; Manufacturer: Vishay-Dale; Power_W: 125mW; TempCo: 200 ppm/C; Value_Code: 6k80; Value: 6.8k; EIA_Code: E24; SizeX_mm: 2; SizeY_mm: 1.25; SizeZ_mm: 1.45; Value2: 0.125W; SizeArea_mm2: 2.5; CompType: Resistor; AEC Qualified: Y; VDC_V: 150V; AEC Category: Q200; AEC Grade: 0
R48 = CMP-0015018-3: RES, 10.0, 1%, 0.5 W, AEC-Q200 Grade 0, 1210; Manufacturer: Vishay-Dale; Power_W: 500mW; TempCo: 100 ppm/C; SizeAreaWB_mm2: 14.7; Value_Code: 10R0; Value: 10.0; EIA_Code: E96; Res_ohm: 10; SizeX_mm: 3.2; SizeY_mm: 2.5; SizeZ_mm: 1.35; Value2: 0.5W; SizeArea_mm2: 8; AEC Qualified: Y; AEC Grade: 0; AEC Category: Q200
R50 = CMP-0017028-3: RES, 4.87 k, 1%, 0.25 W, AEC-Q200 Grade 0, 1206; Manufacturer: Vishay-Dale; Power_W: 250mW; TempCo: 100 ppm/C; Value_Code: 4k87; Value: 4.87k; EIA_Code: E96; SizeX_mm: 3.2; SizeY_mm: 1.6; SizeZ_mm: 1.35; Value2: 0.25W; SizeArea_mm2: 5.12; AEC Qualified: Y; VDC_V: 200V; AEC Category: Q200; AEC Grade: 0
T1 = CMP-0084101-1: Transformer, 2500 uH, TH; Manufacturer: Wurth Elektronik; LeakageInd_H: 55µH; Rsec2_ohm: 0.022; SizeAreaWB_mm2: 1879.488; DCR_ohm: 1.55; Value: 2.5mH; Lp: 2500; SizeZ_mm: 30.48; SizeX_mm: 43.18; SizeY_mm: 39.6; Ns1toNp: 0.0256; SizeArea_mm2: 1709.928; Ns2toNp: 0.0684; AEC Qualified: N; Ns3toNp: 0.11; Rsec1_ohm: 8m; AEC Category: Q200
TP1-TP5 TP7-TP15 = CMP-0055162-1: Test Point, Miniature, SMT; Manufacturer: Keystone; CNHeader: FALSE; Green_Lifecycle: Active; Green_REACh: Passed; CT: TRUE
U1 = CMP-0066030-1: Single-Output LDO, 800mA, Fixed (3.3), Internal Current Limit, Thermal Overload Protection, DCY0004A (SOT-223-4); Alternate Manufacturer: Texas Instruments; Green_Lifecycle: Active; SizeAreaWB_mm2: 76.5; Green_REACh: Passed; U/M: EA; SizeZ_mm: 1.8; SizeX_mm: 7.0; SizeY_mm: 6.5; SizeArea_mm2: 45.5; CompType: IC
U2 = CMP-0067235-2: Constant-Voltage, Constant-Current Flyback Controller Using Opto-Coupler Feedback, D0007A (SOIC-7); Alternate Manufacturer: Texas Instruments; SizeAreaWB_mm2: 55.2; U/M: EA; SizeZ_mm: 1.75; SizeX_mm: 6.0; SizeY_mm: 4.9; SizeArea_mm2: 29.4; CompType: IC; AEC Category: Q200; AEC Qualified: N
U3 = CMP-0006158-3: Optocoupler, 5 kV, 50-600% CTR, SMT; Manufacturer: Lite-On; CTR (Max): 600%; SizeAreaWB_mm2: 80.256; CTR (Min): 50%; SizeZ_mm: 4.6; SizeX_mm: 10.16; SizeArea_mm2: 46.736; Voltage_Isolation_Vrms: 5kV
U4 = CMP-0033147-1: Adjustable Precision Shunt Regulator, 34 ppm / degC, 100 mA, -40 to 85 degC, 3-pin SOT-23 (DBZ), Green (RoHS & no Sb/Br); Manufacturer: Texas Instruments; VO Adj(Max)(V): 36; Temp Coeff(Max)(ppm/ degree C): 92; SubFamily: Shunt Voltage Reference; VO Adj(Min)(V): 2.495; Iout/Iz(Max)(mA): 100; Initial Accuracy @ 25/deg C(%): 0.5; Min Iz for Regulation(uA): 600; Rating: Catalog; Temp Coeff(Typ)(ppm/ degree C): 34

## Sheet TIDA-010000_EVM_Hardware.SchDoc
size 431 x 279 mm; Date: Not shown in title block; ApprovedBy: Not shown in title block; CheckedBy: Not shown in title block; Author: Not shown in title block; CompanyName: Not shown in title block; Engineer: Not shown in title block; Organization: Not shown in title block; Address1: Not shown in title block; Address2: Not shown in title block; Address3: Not shown in title block; Address4: Not shown in title block; DocumentNumber: 1; Revision: Use project parameter SCH_Rev; SheetNumber: 3; SheetTotal: 3; PageSetup: Record=PageOptions¦CenterHorizontal=True¦CenterVertical=True¦PrintScale=1.00¦XCorrection=1.00¦YCorrection=1.00¦PrintKind=0¦BorderSize=5000000¦LeftOffset=0¦BottomOffset=0¦Orientation=2¦PaperLength=1000¦PaperWidth=1000¦Scale=100¦PaperSource=15¦PrintQuality=600¦MediaType=1¦DitherType=10¦PaperKind=Letter¦PrintScaleMode=1
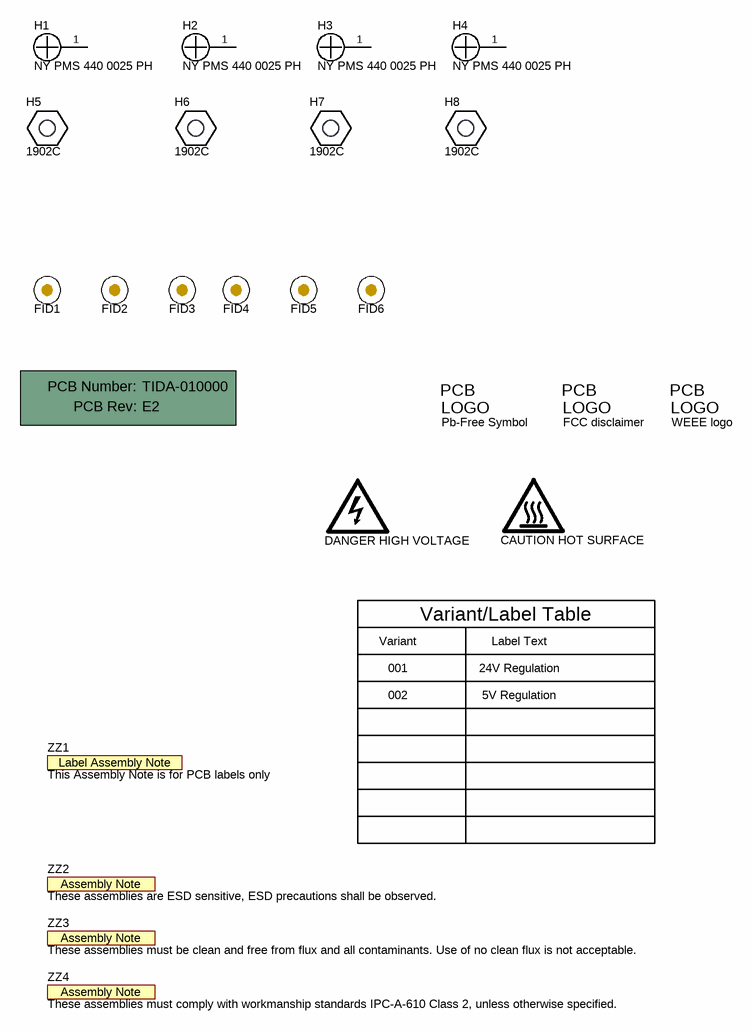
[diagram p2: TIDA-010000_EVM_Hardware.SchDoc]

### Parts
!PCB  Printed Circuit Board  (value not drawn)  (mechanical)
FID1  Fiducial  [Fiducial10-20]  (value not drawn)
FID2  Fiducial  [Fiducial10-20]  (value not drawn)
FID3  Fiducial  [Fiducial10-20]  (value not drawn)
FID4  Fiducial  [Fiducial10-20]  (value not drawn)
FID5  Fiducial  [Fiducial10-20]  (value not drawn)
FID6  Fiducial  [Fiducial10-20]  (value not drawn)
H1  NY PMS 440 0025 PH  [NY PMS 440 0025 PH]
H2  NY PMS 440 0025 PH  [NY PMS 440 0025 PH]
H3  NY PMS 440 0025 PH  [NY PMS 440 0025 PH]
H4  NY PMS 440 0025 PH  [NY PMS 440 0025 PH]
H5  1902C  [Keystone_1902C]
H6  1902C  [Keystone_1902C]
H7  1902C  [Keystone_1902C]
H8  1902C  [Keystone_1902C]
LOGO1  DANGER HIGH VOLTAGE  [IEC_HighVoltage_Small]  (no BOM)
Logo2  Pb-Free Symbol  [Pb-Free_Overlay_Small]  (no BOM)
Logo3  FCC disclaimer  [FCC_disclaimer]  (no BOM)
Logo4  WEEE logo  [WEEE_Minimum]  (no BOM)
LOGO5  CAUTION HOT SURFACE  [IEC_HotSurface_Small]  (no BOM)
ZZ1  This Assembly Note is for PCB labels only  [AssemblyNoteLabel]  (no BOM)
ZZ2  These assemblies are ESD sensitive, ESD precautions shall be observed.  [AssemblyNote]  (no BOM)
ZZ3  These assemblies must be clean and free from flux and all contaminants. Use of no clean flux is not acceptable.  [AssemblyNote]  (no BOM)
ZZ4  These assemblies must comply with workmanship standards IPC-A-610 Class 2, unless otherwise specified.  [AssemblyNote]  (no BOM)

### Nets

Not connected (* = marked no-connect by the designer): H1 1; H2 1; H3 1; H4 1

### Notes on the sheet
- Variant
- Variant/Label Table
- Label Text
- 001
- 002
- 24V Regulation
- 5V Regulation

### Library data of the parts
!PCB = CMP-0003618-2: Manufacturer: Any; PartNumber: TIDA-010000
FID1-FID6 = CMP-0077181-1: Fiducial mark.  There is nothing to buy or mount.
H1-H4 = CMP-0003617-1: Machine Screw, Round, #4-40 x 1/4, Nylon, Philips panhead; Manufacturer: B&F Fastener Supply; CompType: Hardware
H5-H8 = CMP-0003610-1: Standoff, Hex, 0.5"L #4-40 Nylon; Manufacturer: Keystone; CompType: Hardware
LOGO1 = IEC_HighVoltage: IEC 61010-1 High Voltage Warning; SymbolCreator: a0412235
Logo2 = CMP-0074839-1: SymbolCreator: a0412235; Library Reference: Logo
Logo3 = CMP-0074847-1: FCC_disclaimer; Library Reference: Logo
Logo4 = CMP-0074769-1
LOGO5 = IEC_HotSurface: IEC 61010-1 Hot Surface Warning; SymbolCreator: a0412235
ZZ1 = CMP-0003616-3
ZZ2 = CMP-0077236-1
ZZ3 = CMP-0077237-1
ZZ4 = CMP-0077238-1

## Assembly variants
001: not fitted C27 C31 C32 D18 D24 FID1 FID2 FID3 FID4 FID5 FID6 R18 R32 R54
002: not fitted C27 C31 C32 D18 D24 FID1 FID2 FID3 FID4 FID5 FID6 R18 R32 R53; alternate parts R24 -> CMP-0020087-2, R9 -> CMP-0020442-3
